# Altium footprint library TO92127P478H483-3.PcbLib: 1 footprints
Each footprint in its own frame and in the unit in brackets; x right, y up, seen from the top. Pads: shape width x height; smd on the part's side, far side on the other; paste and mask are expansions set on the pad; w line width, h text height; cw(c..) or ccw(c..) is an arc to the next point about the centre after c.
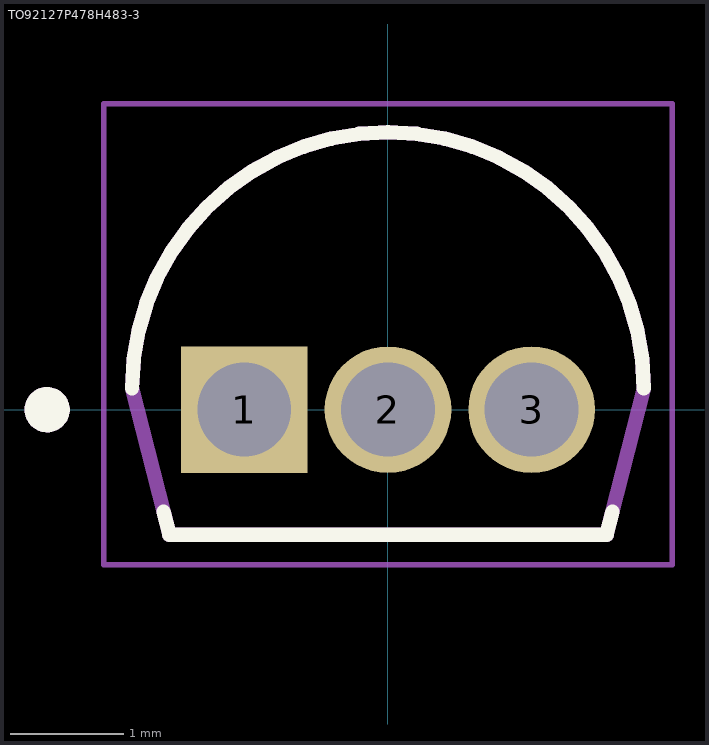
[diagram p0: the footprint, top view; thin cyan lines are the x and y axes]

## TO92127P478H483-3 [mm]
pads (3):
  rect 1.12x1.12 hole 0.83: 1(-1.27,0)
  round 1.12 hole 0.83: 2(0,0) 3(1.27,0)
Top Overlay:
  circle w0.2: c-3.013,0 r0.1
  lines w0.127: -2.262,0.19 cw(c0,0.19) 2.262,0.19 ; -1.984,-0.9 -1.933,-1.105 1.933,-1.105 1.984,-0.9
Mechanical 13:
  circle w0.2: c-3.013,0 r0.1
  lines w0.127: -2.262,0.19 cw(c0,0.19) 2.262,0.19 1.933,-1.105 -1.933,-1.105 -2.262,0.19
Mechanical 15:
  lines w0.05: -2.512,-1.37 2.512,-1.37 2.512,2.703 -2.512,2.703 -2.512,-1.37
3D body "step_temp.STEP": height 5.33, standoff -12.18, extent -2.38,-1.43 2.38,2.19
